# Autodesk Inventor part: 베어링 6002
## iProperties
IsCustomPart: 0
Created: 2009-02
Part Number: 베어링 6002
Material: 강, 연강
Description: 깊은 그루브 볼 베어링
Document SubType Name: Modeling
Standard: KS B 2023
Designer: SeoGD™
Standards Organization: KS
Language: ko-KR
Size Designation: 6002 - 15 x 32 x 9
Categories: <MemberInstance><Categories><Category DisplayName="샤프트 부품" InternalName="7f7aeb1f-a693-4053-b835-cee3144e0d98" Mnemonic="SHFT"><Category DisplayName="베어링" Inter
Density: 1 g/cm^3
Author: SeoGD™
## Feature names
1. IDS_ARRAYBALL[SIMPL:T] [Circular Pattern]
